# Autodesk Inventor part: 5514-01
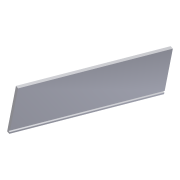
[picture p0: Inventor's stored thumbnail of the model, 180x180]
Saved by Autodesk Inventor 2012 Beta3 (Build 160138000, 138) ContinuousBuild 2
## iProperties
Created: 2011-02
Part Number: 5514-01
Material: Default
Document SubType Name: Modeling
Designer: Beta-8540w
Density: 1 g/cm^3
Author: Beta-8540w
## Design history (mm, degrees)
derived "c15-12.ipt" dims "d2" = 12.7, "d3" = 0, "d4" = 6.35, "d6" = 6.35, "d7" = 0, "width" = 546.1, "height" = 177.8, "thickness" = 6.35
body "Solid1"
feature "Solid1::c15-12.ipt" dims "d2" = 12.7, "d3" = 0, "d4" = 6.35, "d6" = 6.35, "d7" = 0, "width" = 546.1, "height" = 177.8, "thickness" = 6.35, "ScaleForDerivedMember" = 10
tag "TaggingFeature1"
